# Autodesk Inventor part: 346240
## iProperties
Company: Mayer & Müller AG Schaltgeräte
Created: 2005-10
Part Number: 346240
Material: Roccasol 200
Document SubType Name: Modeling
Designer: I.Baliuc
Manufacturer: Standard
Standards Organization: Custom
Description: Isolator
Density: 1.14 g/cm^3
Author: T.Messerschmitt
Comments: Trenner 2005 - 120x120x30 Isoliermasse Roccasol 200 Fa.Irle u. heuel temper. +160°C
Revision Number: 346240
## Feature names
1. Bohrung3 [Hole]
2. Bezeichnung2 [Tagging]
